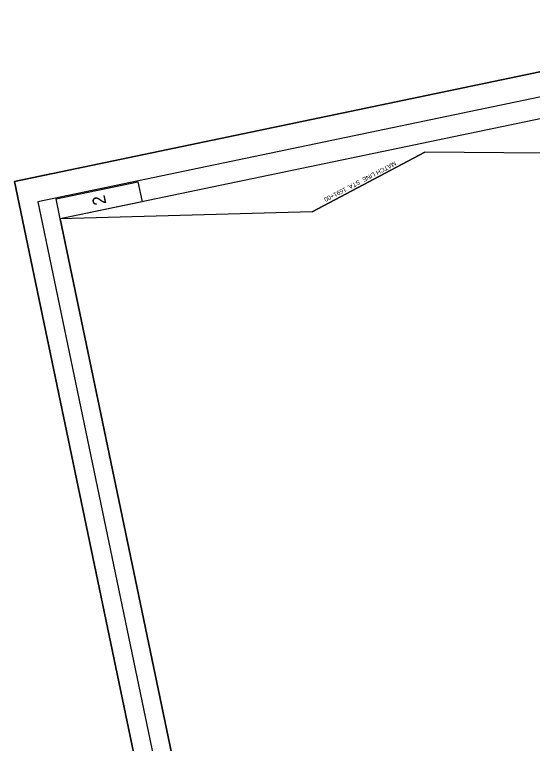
# Model space of a CAD drawing. Extents: x 361335 to 362759, y 126730 to 128619.
# Drawn here: x 361335 to 362032, y 127638 to 128619 of the extents above; entities that cross this region are included whole.
import ezdxf

# ---------------------------------------------------------------- set-up
doc = ezdxf.new("R2010")
doc.units = 0
for name, color, linetype in [('Default', 7, 'Continuous'), ('P_SHTIDX_1 [KAPUR_CADDS_LEVELS]', 7, 'Continuous'), ('P_SHTIDX_2 [KAPUR_CADDS_LEVELS]', 7, 'Continuous'), ('P_SHTIDX_3 [KAPUR_CADDS_LEVELS]', 7, 'Continuous'), ('P_TXT_Plan 1 [KAPUR_CADDS_LEVELS]', 7, 'Continuous'), ('P_TXT_Plan 2 [KAPUR_CADDS_LEVELS]', 7, 'Continuous'), ('P_TXT_Plan 3 [KAPUR_CADDS_LEVELS]', 7, 'Continuous')]:
    doc.layers.add(name, color=color, linetype=linetype)

msp = doc.modelspace()

# ---------------------------------------------------------------- linework, layer by layer
at = {"layer": 'Default'}
msp.add_lwpolyline([(361735.88, 128353.1), (361396.84, 128343.77), (361718.49, 126801.97), (362697.42, 127006.19), (362672.95, 127001.09), (362351.29, 128542.89), (362351.29, 128542.89), (362294.11, 128483.12), (362046.54, 128432.3), (361887.51, 128433.66)], close=True, dxfattribs=at)
msp.add_lwpolyline([(361735.88, 128353.1), (361396.84, 128343.77), (361718.49, 126801.97), (362697.42, 127006.19), (362672.95, 127001.09), (362351.29, 128542.89), (362351.29, 128542.89), (362294.11, 128483.12), (362046.54, 128432.3), (361887.51, 128433.66)], close=True, dxfattribs=at)
msp.add_lwpolyline([(361735.88, 128353.1), (361396.84, 128343.77), (361718.49, 126801.97), (362697.42, 127006.19), (362672.95, 127001.09), (362351.29, 128542.89), (362351.29, 128542.89), (362294.11, 128483.12), (362046.54, 128432.3), (361887.51, 128433.66)], close=True, dxfattribs=at)
msp.add_lwpolyline([(361735.88, 128353.1), (361396.84, 128343.77), (361718.49, 126801.97), (362697.42, 127006.19), (362672.95, 127001.09), (362351.29, 128542.89), (362351.29, 128542.89), (362294.11, 128483.12), (362046.54, 128432.3), (361887.51, 128433.66)], close=True, dxfattribs=at)
msp.add_lwpolyline([(361735.88, 128353.1), (361396.84, 128343.77), (361718.49, 126801.97), (362697.42, 127006.19), (362672.95, 127001.09), (362351.29, 128542.89), (362351.29, 128542.89), (362294.11, 128483.12), (362046.54, 128432.3), (361887.51, 128433.66)], close=True, dxfattribs=at)
msp.add_lwpolyline([(361735.88, 128353.1), (361396.84, 128343.77), (361718.49, 126801.97), (362697.42, 127006.19), (362672.95, 127001.09), (362351.29, 128542.89), (362351.29, 128542.89), (362294.11, 128483.12), (362046.54, 128432.3), (361887.51, 128433.66)], close=True, dxfattribs=at)
msp.add_lwpolyline([(361735.88, 128353.1), (361396.84, 128343.77), (361718.49, 126801.97), (362697.42, 127006.19), (362672.95, 127001.09), (362351.29, 128542.89), (362351.29, 128542.89), (362294.11, 128483.12), (362046.54, 128432.3), (361887.51, 128433.66)], close=True, dxfattribs=at)
msp.add_lwpolyline([(361735.88, 128353.1), (361396.84, 128343.77), (361718.49, 126801.97), (362697.42, 127006.19), (362672.95, 127001.09), (362351.29, 128542.89), (362351.29, 128542.89), (362294.11, 128483.12), (362046.54, 128432.3), (361887.51, 128433.66)], close=True, dxfattribs=at)
msp.add_lwpolyline([(361735.88, 128353.1), (361396.84, 128343.77), (361718.49, 126801.97), (362697.42, 127006.19), (362672.95, 127001.09), (362351.29, 128542.89), (362351.29, 128542.89), (362294.11, 128483.12), (362046.54, 128432.3), (361887.51, 128433.66)], close=True, dxfattribs=at)
msp.add_lwpolyline([(361735.88, 128353.1), (361396.84, 128343.77), (361718.49, 126801.97), (362697.42, 127006.19), (362672.95, 127001.09), (362351.29, 128542.89), (362351.29, 128542.89), (362294.11, 128483.12), (362046.54, 128432.3), (361887.51, 128433.66)], close=True, dxfattribs=at)
at = {"layer": 'P_SHTIDX_1 [KAPUR_CADDS_LEVELS]'}
msp.add_lwpolyline([(361682.47, 126729.84), (361335.28, 128394.01), (362412.1, 128618.66), (362759.28, 126954.49), (361682.47, 126729.84)], dxfattribs=at)
at = {"layer": 'P_SHTIDX_2 [KAPUR_CADDS_LEVELS]'}
for p, q in [((362375.77, 128548), (361396.84, 128343.77)), ((361384.23, 128404.22), (361335.28, 128394.01)), ((361345.5, 128345.06), (361335.28, 128394.01)), ((361718.49, 126801.97), (361396.84, 128343.77))]:
    msp.add_line(p, q, dxfattribs=at)
msp.add_lwpolyline([(361396.84, 128343.77), (361391.23, 128370.69), (361501.35, 128393.67), (361506.97, 128366.75)], close=True, dxfattribs=at)
at = {"layer": 'P_SHTIDX_3 [KAPUR_CADDS_LEVELS]'}
for points in [[(362759.28, 126954.49), (362412.1, 128618.66), (361335.28, 128394.01), (361682.47, 126729.84)], [(362732.36, 126961.13), (362394.37, 128581.25), (361366.5, 128366.81), (361704.49, 126746.69)]]:
    msp.add_lwpolyline(points, close=True, dxfattribs=at)
at = {"layer": 'P_TXT_Plan 2 [KAPUR_CADDS_LEVELS]'}
msp.add_line((361735.88, 128353.1), (361887.51, 128433.66), dxfattribs=at)
at = {"layer": 'P_TXT_Plan 3 [KAPUR_CADDS_LEVELS]'}
msp.add_lwpolyline([(361682.47, 126729.84), (361335.28, 128394.01), (362412.1, 128618.66), (362759.28, 126954.49)], close=True, dxfattribs=at)

# ---------------------------------------------------------------- texts
at = {"layer": 'P_SHTIDX_2 [KAPUR_CADDS_LEVELS]'}
msp.add_text('2', height=17.5, rotation=101.78408, dxfattribs=at).set_placement((361459, 128364.1))
at = {"layer": 'P_TXT_Plan 1 [KAPUR_CADDS_LEVELS]'}
msp.add_text('MATCH LINE  STA. 1691+00', height=6, rotation=207.51469, dxfattribs=at).set_placement((361846.98, 128421.65))

doc.saveas('drawing.dxf')
